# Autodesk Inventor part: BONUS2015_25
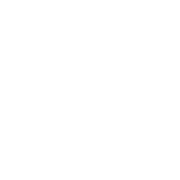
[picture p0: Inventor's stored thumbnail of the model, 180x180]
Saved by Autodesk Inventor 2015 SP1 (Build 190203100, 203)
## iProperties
Created: 2015-05
Part Number: BONUS2015_25
Material: Generisch
Document SubType Name: Modeling
Density: 1 g/cm^3
Appearance: Vorgabe
xx: 25
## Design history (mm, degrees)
